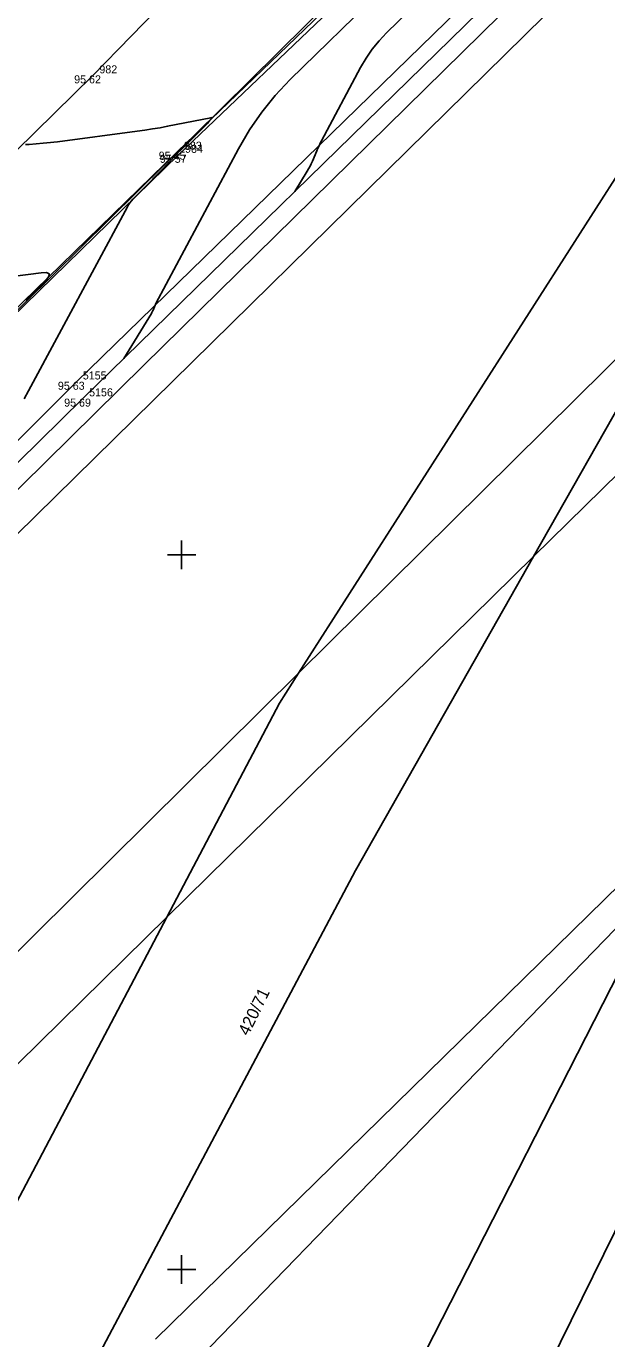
# Model space of a CAD drawing. Extents: x -711081 to -709338, y -1025122 to -1024092.
# Drawn here: x -709555.44 to -709535.12, y -1024302.42 to -1024256.5 of the extents above; entities that cross this region are included whole.
import ezdxf

# ---------------------------------------------------------------- set-up
doc = ezdxf.new("R2010")
doc.units = 0
for name, color, linetype in [('Ex_Major Contours', 7, 'Continuous'), ('Ex_Minor Contours', 7, 'Continuous'), ('Z_body', 7, 'Continuous'), ('Z_body_cisla', 7, 'Continuous'), ('Z_body_vysky_redukovane', 7, 'Continuous'), ('Z_hektometricka_sit', 7, 'Continuous'), ('Z_katastr_cisla_pozemkova', 7, 'Continuous'), ('Z_katastr_hranice', 7, 'Continuous'), ('Z_katastr_vnitrni_kresba', 7, 'Continuous'), ('Z_komunikace', 7, 'Continuous'), ('Z_obruba', 7, 'Continuous'), ('Z_rozhranni', 7, 'Continuous'), ('Z_vdz12_prerusovana', 7, 'Continuous')]:
    doc.layers.add(name, color=color, linetype=linetype)

# ---------------------------------------------------------------- blocks, each defined once
blk = doc.blocks.new('POINT_DISPLAY')
blk.add_line((0, 0), (0, 0))

msp = doc.modelspace()

# ---------------------------------------------------------------- linework, layer by layer
at = {"layer": 'Ex_Major Contours'}
msp.add_lwpolyline([(-709546.036, -1024262.281), (-709545.603, -1024261.573), (-709545.554, -1024261.489), (-709545.507, -1024261.402), (-709545.464, -1024261.314), (-709545.424, -1024261.224), (-709545.271, -1024260.862), (-709545.231, -1024260.772), (-709545.19, -1024260.683), (-709545.147, -1024260.594), (-709545.101, -1024260.507), (-709543.735, -1024257.944), (-709543.544, -1024257.615), (-709543.329, -1024257.304), (-709543.091, -1024257.01), (-709542.829, -1024256.734), (-709541.254, -1024255.192)], dxfattribs=at)
at = {"layer": 'Ex_Minor Contours'}
for points in [[(-709543.058, -1024255.295), (-709546.198, -1024258.369), (-709546.721, -1024258.921), (-709547.198, -1024259.508), (-709547.627, -1024260.13), (-709548.01, -1024260.788), (-709550.898, -1024266.205), (-709550.912, -1024266.233), (-709550.926, -1024266.262), (-709550.94, -1024266.291), (-709550.953, -1024266.32), (-709551.002, -1024266.438), (-709551.015, -1024266.467), (-709551.029, -1024266.495), (-709551.044, -1024266.523), (-709551.061, -1024266.551), (-709552.023, -1024268.127)], [(-709555.514, -1024269.542), (-709555.362, -1024269.257), (-709551.901, -1024262.818), (-709551.859, -1024262.746), (-709551.812, -1024262.677), (-709551.76, -1024262.612), (-709551.703, -1024262.55), (-709551.467, -1024262.311), (-709551.408, -1024262.251), (-709551.35, -1024262.191), (-709551.291, -1024262.131), (-709551.232, -1024262.07), (-709550.384, -1024261.195), (-709550.259, -1024261.066), (-709550.132, -1024260.937), (-709550.005, -1024260.809), (-709549.877, -1024260.682), (-709549.164, -1024259.975), (-709549.136, -1024259.947), (-709549.109, -1024259.919), (-709549.082, -1024259.891), (-709549.056, -1024259.862), (-709548.952, -1024259.746), (-709548.934, -1024259.722), (-709548.932, -1024259.706), (-709548.946, -1024259.7), (-709548.976, -1024259.703), (-709550.49, -1024260.001), (-709550.756, -1024260.051), (-709551.022, -1024260.096), (-709551.289, -1024260.138), (-709551.556, -1024260.176), (-709554.349, -1024260.546), (-709554.473, -1024260.562), (-709554.596, -1024260.575), (-709554.72, -1024260.587), (-709554.844, -1024260.597), (-709555.34, -1024260.635), (-709555.464, -1024260.638)], [(-709556.931, -1024265.392), (-709554.913, -1024265.125), (-709554.725, -1024265.119), (-709554.639, -1024265.164), (-709554.654, -1024265.26), (-709554.771, -1024265.407), (-709555.441, -1024266.099)]]:
    msp.add_lwpolyline(points, dxfattribs=at)
at = {"layer": 'Z_hektometricka_sit'}
for p, q in [((-709550, -1024274.5), (-709550, -1024275.5)), ((-709550.5, -1024275), (-709549.5, -1024275)), ((-709550, -1024299.5), (-709550, -1024300.5)), ((-709550.5, -1024300), (-709549.5, -1024300))]:
    msp.add_line(p, q, dxfattribs=at)
at = {"layer": 'Z_katastr_hranice'}
for p, q in [((-709537.89, -1024255.17), (-709551.32, -1024268.36)), ((-709545.91, -1024279.14), (-709531.46, -1024256.57)), ((-709537.68, -1024275.05), (-709532.44, -1024265.81)), ((-709551.32, -1024268.36), (-709571.21, -1024287.91)), ((-709543.91, -1024286.04), (-709537.68, -1024275.05)), ((-709546.58, -1024280.18), (-709545.91, -1024279.14)), ((-709550.52, -1024287.67), (-709546.58, -1024280.18)), ((-709528.47, -1024285.73), (-709537.12, -1024303.32)), ((-709554.59, -1024306.15), (-709543.91, -1024286.04)), ((-709549.76, -1024303.48), (-709533.11, -1024286.32)), ((-709560.66, -1024306.9), (-709550.52, -1024287.67))]:
    msp.add_line(p, q, dxfattribs=at)
at = {"layer": 'Z_katastr_vnitrni_kresba'}
for p, q in [((-709573.42, -1024283.89), (-709543.18, -1024254.02)), ((-709570.66, -1024288.9), (-709536.6, -1024255.45)), ((-709537.68, -1024275.05), (-709521.16, -1024258.83)), ((-709545.91, -1024279.14), (-709532.44, -1024265.81)), ((-709523.18, -1024275.29), (-709550.92, -1024302.44)), ((-709550.52, -1024287.67), (-709537.68, -1024275.05)), ((-709563.57, -1024296.61), (-709545.91, -1024279.14)), ((-709545.72, -1024311.19), (-709532.94, -1024286.16)), ((-709558.99, -1024295.98), (-709550.52, -1024287.67))]:
    msp.add_line(p, q, dxfattribs=at)
at = {"layer": 'Z_komunikace'}
for p, q in [((-709550.15, -1024260.89), (-709543.9, -1024254.88)), ((-709553.46, -1024269.53), (-709539.09, -1024255.5)), ((-709562.15, -1024272.57), (-709550.15, -1024260.89)), ((-709568.18, -1024283.96), (-709553.46, -1024269.53))]:
    msp.add_line(p, q, dxfattribs=at)
at = {"layer": 'Z_obruba'}
for p, q in [((-709550.11, -1024261), (-709543.9, -1024255.07)), ((-709562.09, -1024272.69), (-709550.11, -1024261))]:
    msp.add_line(p, q, dxfattribs=at)
at = {"layer": 'Z_rozhranni'}
for p, q in [((-709553.68, -1024268.94), (-709539.46, -1024255.1)), ((-709568.41, -1024283.6), (-709553.68, -1024268.94))]:
    msp.add_line(p, q, dxfattribs=at)
at = {"layer": 'Z_vdz12_prerusovana'}
for p, q in [((-709553.11, -1024258.22), (-709541.24, -1024246.03)), ((-709565.09, -1024269.98), (-709553.11, -1024258.22))]:
    msp.add_line(p, q, dxfattribs=at)

# ---------------------------------------------------------------- block references
at = {"layer": 'Z_body'}
for p in [(-709553.11, -1024258.22), (-709550.15, -1024260.89), (-709550.11, -1024261), (-709553.68, -1024268.94), (-709553.46, -1024269.53)]:
    msp.add_blockref('POINT_DISPLAY', p, dxfattribs=at)

# ---------------------------------------------------------------- texts
at = {"layer": 'Z_body_cisla'}
for s, p in [('982', (-709552.88, -1024258.15)), ('983', (-709549.92, -1024260.82)), ('984', (-709549.88, -1024260.93)), ('5155', (-709553.46, -1024268.86)), ('5156', (-709553.24, -1024269.45))]:
    msp.add_text(s, height=0.28, dxfattribs=at).set_placement(p)
at = {"layer": 'Z_body_vysky_redukovane'}
for s, p in [('95 62', (-709553.763, -1024258.5)), ('95 45', (-709550.803, -1024261.17)), ('95 57', (-709550.763, -1024261.28)), ('95 63', (-709554.333, -1024269.22)), ('95 69', (-709554.113, -1024269.81))]:
    msp.add_text(s, height=0.28, dxfattribs=at).set_placement(p)
at = {"layer": 'Z_katastr_cisla_pozemkova'}
msp.add_text('420/71', height=0.425, rotation=64, dxfattribs=at).set_placement((-709547.664, -1024291.848))

doc.saveas('drawing.dxf')
